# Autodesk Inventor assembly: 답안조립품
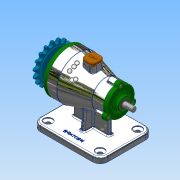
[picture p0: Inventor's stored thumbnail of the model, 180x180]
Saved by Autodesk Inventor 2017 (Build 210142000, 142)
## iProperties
Part Number: 답안조립품
Material: 일반
Document SubType Name: Assembly
Designer: user
Author: user
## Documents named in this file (16)
- C:\Users\user\Desktop\711006V1015\답안조립품.iam
- C:\Users\user\Desktop\711006V1015\본체.ipt
- C:\Users\user\Desktop\711006V1015\뒤커버.ipt
- C:\Users\user\Desktop\711006V1015\앞커버.ipt
- C:\Users\user\Desktop\711006V1015\오일 실 17x30x8.ipt
- C:\Users\user\Desktop\711006V1015\축.ipt
- C:\Users\user\Desktop\711006V1015\오일 실 10x20x7.ipt
- C:\Users\user\Desktop\711006V1015\베어링 6203.ipt
- C:\Users\user\Desktop\711006V1015\베어링 6200.ipt
- C:\Users\user\Desktop\711006V1015\키 5x5.ipt
- 키 5 x 5.ipt
- C:\Users\user\Desktop\711006V1015\스프로킷.ipt
- C:\Users\user\Desktop\711006V1015\마개.ipt
- C:\Users\user\Desktop\711006V1015\와셔.ipt
- C:\Users\user\Desktop\711006V1015\볼트 M4.ipt
- 볼트 M4 x 12.ipt
